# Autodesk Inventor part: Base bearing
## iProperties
Created: 2006-10
Part Number: Base bearing
Document SubType Name: Modeling
Designer: John Croya
Density: 1 g/cm^3
Control State: 0
Master: False
Checked Out: False
Shininess: 64.0
Angle Display Precision: 2
Document Length Units: 11272
Document Angle Units: 11279
Document Time Units: 11290
Document Mass Units: 11286
Document Length Units Precision: 3
Document Angle Units Precision: 2
Compacted: False
Density: 0.0
Volumn: 0.0
Area: 0.0
PropertySet Name: Model Information
Author: John Croya
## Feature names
1. Revolution1
